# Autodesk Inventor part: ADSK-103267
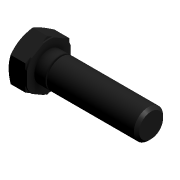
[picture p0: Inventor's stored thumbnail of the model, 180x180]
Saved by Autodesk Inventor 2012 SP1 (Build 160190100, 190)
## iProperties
Created: 2000-08
Part Number: ADSK-103267
Description: Hex Cap Screw
Document SubType Name: Modeling
Standard: ANSI B18.2.1 - 1/2 - 13 - 1 3/4
Designer: gao
Density: 1 g/cm^3
Material: Default
Control State: 0
Master: False
Checked Out: False
Shininess: 0.0
Density: 0.0
Volumn: 0.0
Area: 0.0
PropertySet Name: Model Information
Author: gao
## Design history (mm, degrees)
node "Base1"
body "Solid1"
